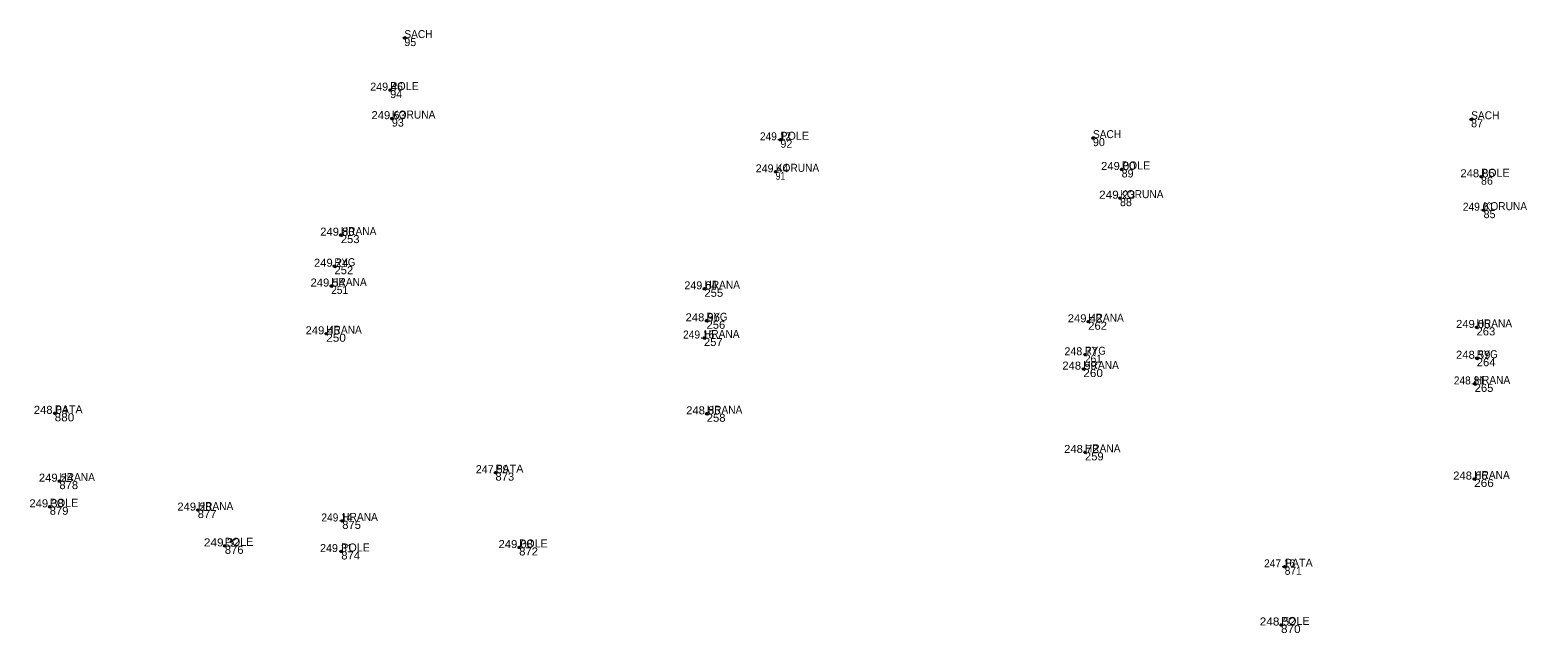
# Model space of a CAD drawing. Extents: x -565336 to -561834, y -1146819 to -1145270.
# Drawn here: x -562427.8 to -562364.2, y -1145638.5 to -1145612.9 of the extents above; entities that cross this region are included whole.
import ezdxf
from ezdxf.enums import TextEntityAlignment as Align

# ---------------------------------------------------------------- set-up
doc = ezdxf.new("R2010")
doc.units = 0
doc.header["$LTSCALE"] = 0.14
doc.header["$PDMODE"] = 32
doc.header["$PDSIZE"] = 0.07
for name, color, linetype in [('40', 7, 'Continuous'), ('43', 7, 'Continuous'), ('44', 7, 'Continuous'), ('45', 7, 'Continuous')]:
    doc.layers.add(name, color=color, linetype=linetype)

msp = doc.modelspace()

# ---------------------------------------------------------------- linework, layer by layer
at = {"layer": '40'}
for p in [(-562411.91, -1145613.27), (-562412.51, -1145615.48), (-562412.44, -1145616.69), (-562366.58, -1145616.72), (-562395.93, -1145617.59), (-562382.65, -1145617.52), (-562396.13, -1145618.95), (-562381.43, -1145618.85), (-562366.16, -1145619.16), (-562381.5, -1145620.07), (-562366.05, -1145620.58), (-562414.61, -1145621.64), (-562414.88, -1145622.96), (-562415.02, -1145623.8), (-562399.16, -1145623.92), (-562399.07, -1145625.28), (-562382.85, -1145625.32), (-562366.35, -1145625.56), (-562415.23, -1145625.83), (-562399.18, -1145626.01), (-562382.99, -1145626.72), (-562366.34, -1145626.87), (-562383.06, -1145627.33), (-562366.43, -1145627.96), (-562426.77, -1145629.21), (-562399.06, -1145629.23), (-562382.99, -1145630.87), (-562426.57, -1145632.09), (-562408.04, -1145631.73), (-562366.45, -1145632), (-562426.98, -1145633.18), (-562420.69, -1145633.32), (-562414.55, -1145633.78), (-562419.54, -1145634.84), (-562414.59, -1145635.08), (-562407.03, -1145634.91), (-562374.5, -1145635.73), (-562374.66, -1145638.2)]:
    msp.add_point(p, dxfattribs=at)

# ---------------------------------------------------------------- texts
at = {"layer": '43'}
for s, p in [('95', (-562411.91, -1145613.61)), ('94', (-562412.51, -1145615.82)), ('93', (-562412.44, -1145617.03)), ('87', (-562366.58, -1145617.06)), ('92', (-562395.93, -1145617.93)), ('90', (-562382.65, -1145617.86)), ('89', (-562381.43, -1145619.19)), ('86', (-562366.16, -1145619.5)), ('88', (-562381.5, -1145620.41)), ('85', (-562366.05, -1145620.92))]:
    msp.add_text(s, height=0.34, dxfattribs=at).set_placement(p)
for s, width, p in [('91', 0.8, (-562396.13, -1145619.29)), ('253', 1.05, (-562414.61, -1145621.98)), ('252', 1.05, (-562414.88, -1145623.3)), ('251', 0.95, (-562415.02, -1145624.14)), ('255', 1.05, (-562399.16, -1145624.26)), ('256', 1.05, (-562399.07, -1145625.62)), ('262', 1.05, (-562382.85, -1145625.66)), ('263', 1.05, (-562366.35, -1145625.9)), ('250', 1.1, (-562415.23, -1145626.17)), ('257', 1.05, (-562399.18, -1145626.35)), ('261', 0.95, (-562382.99, -1145627.06)), ('264', 1.05, (-562366.34, -1145627.21)), ('260', 1.1, (-562383.06, -1145627.67)), ('265', 1.05, (-562366.43, -1145628.3)), ('880', 1.1, (-562426.77, -1145629.55)), ('258', 1.05, (-562399.06, -1145629.57)), ('259', 1.05, (-562382.99, -1145631.21)), ('873', 1.05, (-562408.04, -1145632.07)), ('266', 1.1, (-562366.45, -1145632.34)), ('878', 1.05, (-562426.57, -1145632.43)), ('879', 1.05, (-562426.98, -1145633.52)), ('877', 1.05, (-562420.69, -1145633.66)), ('875', 1.05, (-562414.55, -1145634.12)), ('876', 1.05, (-562419.54, -1145635.18)), ('874', 1.05, (-562414.59, -1145635.42)), ('872', 1.05, (-562407.03, -1145635.25)), ('871', 0.95, (-562374.5, -1145636.07)), ('870', 1.1, (-562374.66, -1145638.54))]:
    msp.add_text(s, height=0.34, dxfattribs=dict(at, width=width)).set_placement(p)
at = {"layer": '44'}
for s, p in [('249.46', (-562412.665, -1145615.504)), ('249.44', (-562396.285, -1145618.974)), ('249.64', (-562399.315, -1145623.944)), ('248.77', (-562383.167, -1145626.744)), ('247.59', (-562408.178, -1145631.754)), ('249.31', (-562414.7975, -1145635.104))]:
    msp.add_text(s, height=0.34, dxfattribs=at).set_placement(p, align=Align.CENTER)
for s, width, p in [('249.63', 1.05, (-562412.578, -1145616.714)), ('249.12', 0.95, (-562396.14, -1145617.614)), ('249.00', 1.05, (-562381.5745, -1145618.874)), ('248.85', 1.05, (-562366.306, -1145619.184)), ('249.23', 1.1, (-562381.623, -1145620.094)), ('249.01', 0.95, (-562366.2695, -1145620.604)), ('249.80', 1.05, (-562414.7545, -1145621.664)), ('249.24', 1.05, (-562415.0205, -1145622.984)), ('249.54', 1.05, (-562415.166, -1145623.824)), ('248.96', 1.05, (-562399.2305, -1145625.304)), ('249.42', 1.05, (-562382.9905, -1145625.344)), ('249.45', 1.05, (-562415.376, -1145625.854)), ('249.16', 0.95, (-562399.405, -1145626.034)), ('249.05', 1.05, (-562366.4905, -1145625.584)), ('248.59', 1.05, (-562366.4915, -1145626.894)), ('248.99', 1.05, (-562383.2205, -1145627.354)), ('248.81', 0.95, (-562366.655, -1145627.984)), ('248.04', 1.05, (-562426.9255, -1145629.234)), ('248.85', 1.05, (-562399.206, -1145629.254)), ('248.72', 1.05, (-562383.144, -1145630.894)), ('249.24', 1.05, (-562426.7105, -1145632.114)), ('248.66', 1.05, (-562366.6105, -1145632.024)), ('249.38', 1.05, (-562427.114, -1145633.204)), ('249.28', 1.05, (-562420.8265, -1145633.344)), ('249.14', 0.95, (-562414.775, -1145633.804)), ('249.32', 1.1, (-562419.663, -1145634.864)), ('249.08', 1.05, (-562407.176, -1145634.934)), ('247.16', 0.95, (-562374.717, -1145635.754)), ('248.52', 1.1, (-562374.7965, -1145638.224))]:
    msp.add_text(s, height=0.34, dxfattribs=dict(at, width=width)).set_placement(p, align=Align.CENTER)
at = {"layer": '45'}
for s, width, p in [('SACH', 0.95, (-562411.91, -1145613.27)), ('KORUNA', 0.95, (-562412.44, -1145616.69)), ('SACH', 0.95, (-562366.58, -1145616.72)), ('SACH', 0.95, (-562382.65, -1145617.52)), ('KORUNA', 0.95, (-562396.13, -1145618.95)), ('KORUNA', 0.95, (-562381.5, -1145620.07)), ('KORUNA', 0.95, (-562366.05, -1145620.58)), ('HRANA', 0.95, (-562414.61, -1145621.64)), ('RYG', 0.9, (-562414.88, -1145622.96)), ('HRANA', 0.95, (-562415.02, -1145623.8)), ('HRANA', 0.95, (-562399.16, -1145623.92)), ('RYG', 0.9, (-562399.07, -1145625.28)), ('HRANA', 0.95, (-562382.85, -1145625.32)), ('HRANA', 0.95, (-562415.23, -1145625.83)), ('HRANA', 0.95, (-562399.18, -1145626.01)), ('HRANA', 0.95, (-562366.35, -1145625.56)), ('RYG', 0.9, (-562382.99, -1145626.72)), ('RYG', 0.9, (-562366.34, -1145626.87)), ('HRANA', 0.95, (-562383.06, -1145627.33)), ('HRANA', 0.95, (-562366.43, -1145627.96)), ('HRANA', 0.95, (-562399.06, -1145629.23)), ('HRANA', 0.95, (-562382.99, -1145630.87)), ('HRANA', 0.95, (-562426.57, -1145632.09)), ('HRANA', 0.95, (-562366.45, -1145632)), ('HRANA', 0.95, (-562420.69, -1145633.32)), ('HRANA', 0.95, (-562414.55, -1145633.78))]:
    msp.add_text(s, height=0.34, dxfattribs=dict(at, width=width)).set_placement(p)
for s, p in [('POLE', (-562412.51, -1145615.48)), ('POLE', (-562395.93, -1145617.59)), ('POLE', (-562381.43, -1145618.85)), ('POLE', (-562366.16, -1145619.16)), ('PATA', (-562426.77, -1145629.21)), ('PATA', (-562408.04, -1145631.73)), ('POLE', (-562426.98, -1145633.18)), ('POLE', (-562419.54, -1145634.84)), ('POLE', (-562407.03, -1145634.91)), ('POLE', (-562414.59, -1145635.08)), ('PATA', (-562374.5, -1145635.73)), ('POLE', (-562374.66, -1145638.2))]:
    msp.add_text(s, height=0.34, dxfattribs=at).set_placement(p)

doc.saveas('drawing.dxf')
